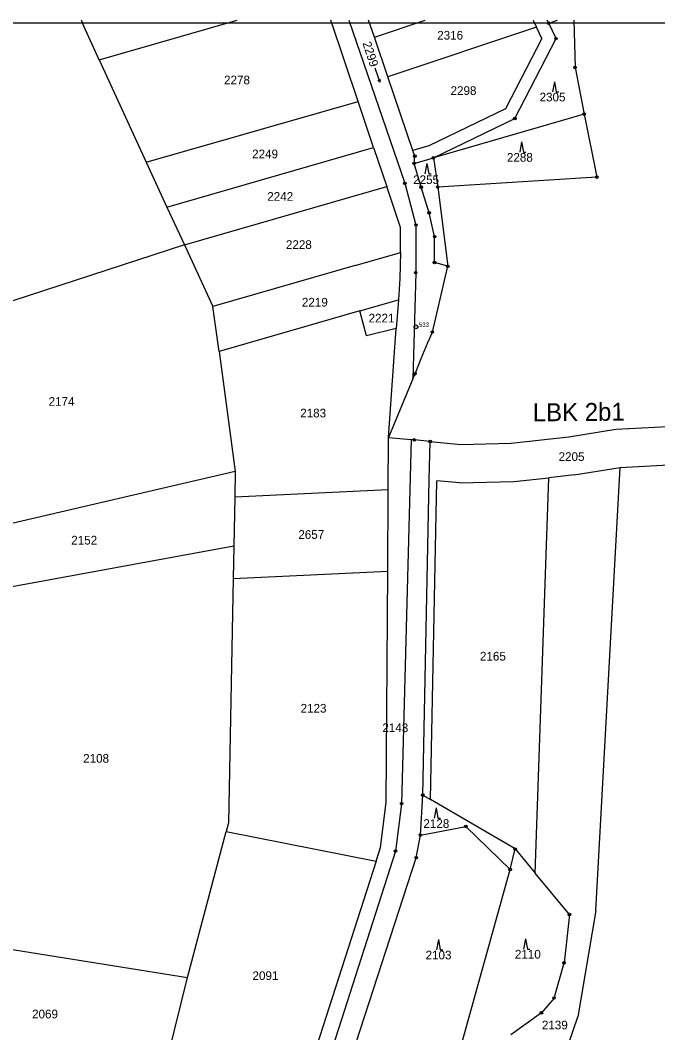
# Model space of a CAD drawing. Extents: x -566461 to -565197, y -1096302 to -1095706.
# Drawn here: x -565802.3 to -565553.3, y -1096101.6 to -1095706 of the extents above; entities that cross this region are included whole.
import ezdxf

# ---------------------------------------------------------------- set-up
doc = ezdxf.new("R2010")
doc.units = 0
for name, color, linetype in [('Vrstva 1', 7, 'Continuous'), ('Vrstva 13', 7, 'Continuous'), ('Vrstva 17', 7, 'Continuous'), ('Vrstva 18', 7, 'Continuous'), ('Vrstva 24', 7, 'Continuous'), ('Vrstva 25', 7, 'Continuous'), ('Vrstva 63', 7, 'Continuous')]:
    doc.layers.add(name, color=color, linetype=linetype)

msp = doc.modelspace()

# ---------------------------------------------------------------- linework, layer by layer
at = {"layer": 'Vrstva 1'}
for p, q in [((-565777.54, -1095708.35), (-565778.44, -1095705.99)), ((-565771.47, -1095721.51), (-565777.54, -1095708.35)), ((-565771.47, -1095721.51), (-565717.56, -1095705.99)), ((-565670.31, -1095737.74), (-565680.99, -1095705.99)), ((-565673.99, -1095705.99), (-565652.1, -1095769.69)), ((-565663.97, -1095712.64), (-565666.23, -1095705.99)), ((-565663.97, -1095712.64), (-565644.16, -1095705.99)), ((-565600.65, -1095708.75), (-565658.72, -1095728.1)), ((-565601.97, -1095705.99), (-565600.65, -1095708.75)), ((-565598.58, -1095713.08), (-565600.65, -1095708.75)), ((-565595.87, -1095707.16), (-565596.43, -1095705.99)), ((-565595.87, -1095707.16), (-565592.37, -1095705.99)), ((-565593, -1095713.17), (-565595.87, -1095707.16)), ((-565658.72, -1095728.1), (-565663.97, -1095712.64)), ((-565598.58, -1095713.08), (-565612.8, -1095740.59)), ((-565609.12, -1095744.37), (-565593, -1095713.17)), ((-565771.47, -1095721.51), (-565753.07, -1095761.44)), ((-565648.94, -1095756.88), (-565658.72, -1095728.1)), ((-565753.07, -1095761.44), (-565670.31, -1095737.74)), ((-565664.25, -1095755.72), (-565670.31, -1095737.74)), ((-565612.8, -1095740.59), (-565642.72, -1095755.05)), ((-565581.98, -1095742.65), (-565640.92, -1095759.74)), ((-565640.92, -1095759.74), (-565609.12, -1095744.37)), ((-565744.99, -1095778.97), (-565664.25, -1095755.72)), ((-565664.25, -1095755.72), (-565659.11, -1095770.99)), ((-565642.72, -1095755.05), (-565648.94, -1095756.88)), ((-565648.18, -1095759.12), (-565648.94, -1095756.88)), ((-565648.45, -1095761.92), (-565648.18, -1095759.12)), ((-565648.45, -1095761.92), (-565640.92, -1095759.74)), ((-565640.92, -1095759.74), (-565639.24, -1095771.17)), ((-565753.07, -1095761.44), (-565744.99, -1095778.97)), ((-565645.7, -1095771.21), (-565648.45, -1095761.92)), ((-565738.18, -1095793.75), (-565659.11, -1095770.99)), ((-565653.73, -1095786.97), (-565659.11, -1095770.99)), ((-565652.1, -1095769.69), (-565647.72, -1095786)), ((-565642.59, -1095781.22), (-565645.7, -1095771.21)), ((-565744.99, -1095778.97), (-565738.18, -1095793.75)), ((-565640.43, -1095790.53), (-565642.59, -1095781.22)), ((-565653.78, -1095796.72), (-565653.73, -1095786.97)), ((-565647.72, -1095786), (-565647.82, -1095804.63)), ((-565640.52, -1095800.66), (-565640.43, -1095790.53)), ((-565738.18, -1095793.75), (-565857.02, -1095832.44)), ((-565738.18, -1095793.75), (-565727.08, -1095817.82)), ((-565671.46, -1095801.81), (-565653.78, -1095796.72)), ((-565653.78, -1095796.72), (-565653.99, -1095806.9)), ((-565671.46, -1095801.81), (-565727.08, -1095817.82)), ((-565635.28, -1095802.11), (-565640.52, -1095800.66)), ((-565653.99, -1095806.9), (-565654.59, -1095815.19)), ((-565647.82, -1095804.63), (-565648.92, -1095846.12)), ((-565669.64, -1095819.55), (-565654.59, -1095815.19)), ((-565654.59, -1095815.19), (-565655.4, -1095826.46)), ((-565724.6, -1095835.47), (-565727.08, -1095817.82)), ((-565669.64, -1095819.55), (-565724.6, -1095835.47)), ((-565667.04, -1095829.24), (-565669.64, -1095819.55)), ((-565655.4, -1095826.46), (-565667.04, -1095829.24)), ((-565658.43, -1095868.97), (-565655.4, -1095826.46)), ((-565724.6, -1095835.47), (-565718.36, -1095882.24)), ((-565658.56, -1095889.49), (-565658.43, -1095868.97)), ((-565649.55, -1095869.85), (-565653.34, -1096012.12)), ((-565642.52, -1095885.6), (-565642.21, -1095870.56)), ((-565568.01, -1095880.69), (-565521.32, -1095878.21)), ((-565718.36, -1095882.24), (-565836.03, -1095909.77)), ((-565718.36, -1095882.24), (-565718.55, -1095892.34)), ((-565585.92, -1095883.62), (-565568.01, -1095880.69)), ((-565577.48, -1096053.89), (-565568.01, -1095880.69)), ((-565645.08, -1096008.78), (-565642.52, -1095885.6)), ((-565642.11, -1096010.51), (-565639.56, -1095885.89)), ((-565630.78, -1095886.75), (-565639.56, -1095885.89)), ((-565630.78, -1095886.75), (-565609.49, -1095886.27)), ((-565609.49, -1095886.27), (-565595.88, -1095884.74)), ((-565601.21, -1096039.18), (-565595.88, -1095884.74)), ((-565585.92, -1095883.62), (-565595.88, -1095884.74)), ((-565658.56, -1095889.49), (-565718.55, -1095892.34)), ((-565658.76, -1095921.2), (-565658.56, -1095889.49)), ((-565718.55, -1095892.34), (-565718.91, -1095911.52)), ((-565718.91, -1095911.52), (-565830.02, -1095931.91)), ((-565718.91, -1095911.52), (-565719.15, -1095924.11)), ((-565719.15, -1095924.11), (-565658.76, -1095921.2)), ((-565659.33, -1096011.65), (-565658.76, -1095921.2)), ((-565719.15, -1095924.11), (-565720.97, -1096019.59)), ((-565646, -1096024.36), (-565645.08, -1096008.78)), ((-565645.08, -1096008.78), (-565642.11, -1096010.51)), ((-565661.61, -1096029.27), (-565659.33, -1096011.65)), ((-565653.34, -1096012.12), (-565655.73, -1096030.58)), ((-565608.98, -1096029.79), (-565642.11, -1096010.51)), ((-565720.97, -1096019.59), (-565721.87, -1096022.99)), ((-565646, -1096024.36), (-565628.24, -1096020.97)), ((-565610.93, -1096037.81), (-565628.24, -1096020.97)), ((-565736.97, -1096079.98), (-565721.87, -1096022.99)), ((-565721.87, -1096022.99), (-565663.31, -1096034.56)), ((-565647.61, -1096033.2), (-565646, -1096024.36)), ((-565663.31, -1096034.56), (-565661.61, -1096029.27)), ((-565655.73, -1096030.58), (-565691.34, -1096141.44)), ((-565678.86, -1096129.12), (-565647.61, -1096033.2)), ((-565610.93, -1096037.81), (-565608.98, -1096029.79)), ((-565608.98, -1096029.79), (-565601.21, -1096039.18)), ((-565663.31, -1096034.56), (-565696.05, -1096136.4)), ((-565630.9, -1096109.42), (-565610.93, -1096037.81)), ((-565587.78, -1096055.41), (-565601.21, -1096039.18)), ((-565587.78, -1096055.41), (-565589.89, -1096074.25)), ((-565577.48, -1096053.89), (-565584.54, -1096095.4)), ((-565838.03, -1096063.98), (-565736.97, -1096079.98)), ((-565593.78, -1096088.03), (-565589.89, -1096074.25)), ((-565748.22, -1096125.78), (-565736.97, -1096079.98)), ((-565593.78, -1096088.03), (-565598.72, -1096093.8)), ((-565642.73, -1096265.59), (-565584.54, -1096095.4)), ((-565598.72, -1096093.8), (-565610.72, -1096102.41))]:
    msp.add_line(p, q, dxfattribs=at)
at = {"layer": 'Vrstva 13'}
for p, q in [((-565586.08, -1095705.99), (-565585.59, -1095724.47)), ((-565585.59, -1095724.47), (-565581.98, -1095742.65)), ((-565581.98, -1095742.65), (-565577.09, -1095767.26)), ((-565577.09, -1095767.26), (-565639.24, -1095771.17)), ((-565639.24, -1095771.17), (-565635.28, -1095802.11)), ((-565641.32, -1095827.8), (-565635.28, -1095802.11)), ((-565643.04, -1095831.96), (-565641.32, -1095827.8)), ((-565645.64, -1095838.21), (-565643.04, -1095831.96)), ((-565648.08, -1095844.1), (-565645.64, -1095838.21)), ((-565648.92, -1095846.12), (-565658.43, -1095868.97)), ((-565648.92, -1095846.12), (-565648.08, -1095844.1)), ((-565569.62, -1095865.76), (-565522.03, -1095863.23)), ((-565587.97, -1095868.76), (-565569.62, -1095865.76)), ((-565658.43, -1095868.97), (-565649.55, -1095869.85)), ((-565648.38, -1095869.96), (-565649.55, -1095869.85)), ((-565642.21, -1095870.56), (-565648.38, -1095869.96)), ((-565642.21, -1095870.56), (-565630.22, -1095871.73)), ((-565630.22, -1095871.73), (-565610.5, -1095871.29)), ((-565610.5, -1095871.29), (-565587.97, -1095868.76))]:
    msp.add_line(p, q, dxfattribs=at)
at = {"layer": 'Vrstva 24'}
for centre, radius in [((-565595.87, -1095707.16), 0.5), ((-565595.87, -1095707.16), 0.0327), ((-565593, -1095713.17), 0.5), ((-565593, -1095713.17), 0.0327), ((-565585.59, -1095724.47), 0.5), ((-565585.59, -1095724.47), 0.0327), ((-565609.12, -1095744.37), 0.5), ((-565609.12, -1095744.37), 0.0327), ((-565581.98, -1095742.65), 0.5), ((-565581.98, -1095742.65), 0.0327), ((-565648.18, -1095759.12), 0.5), ((-565648.18, -1095759.12), 0.0327), ((-565640.92, -1095759.74), 0.5), ((-565640.92, -1095759.74), 0.0327), ((-565648.45, -1095761.92), 0.5), ((-565648.45, -1095761.92), 0.0327), ((-565577.09, -1095767.26), 0.5), ((-565577.09, -1095767.26), 0.0327), ((-565652.1, -1095769.69), 0.5), ((-565652.1, -1095769.69), 0.0327), ((-565645.7, -1095771.21), 0.5), ((-565645.7, -1095771.21), 0.0327), ((-565639.24, -1095771.17), 0.5), ((-565639.24, -1095771.17), 0.0327), ((-565642.59, -1095781.22), 0.5), ((-565642.59, -1095781.22), 0.0327), ((-565647.72, -1095786), 0.5), ((-565647.72, -1095786), 0.0327), ((-565640.43, -1095790.53), 0.5), ((-565640.43, -1095790.53), 0.0327), ((-565640.52, -1095800.66), 0.5), ((-565640.52, -1095800.66), 0.0327), ((-565635.28, -1095802.11), 0.5), ((-565635.28, -1095802.11), 0.0327), ((-565647.82, -1095804.63), 0.5), ((-565647.82, -1095804.63), 0.0327), ((-565647.73, -1095825.8), 0.75), ((-565647.73, -1095825.8), 0.0327), ((-565641.32, -1095827.8), 0.5), ((-565641.32, -1095827.8), 0.0327), ((-565648.08, -1095844.1), 0.5), ((-565648.08, -1095844.1), 0.0327), ((-565648.38, -1095869.96), 0.5), ((-565648.38, -1095869.96), 0.0327), ((-565642.21, -1095870.56), 0.5), ((-565642.21, -1095870.56), 0.0327), ((-565645.08, -1096008.78), 0.5), ((-565645.08, -1096008.78), 0.0327), ((-565653.34, -1096012.12), 0.5), ((-565653.34, -1096012.12), 0.0327), ((-565628.24, -1096020.97), 0.5), ((-565628.24, -1096020.97), 0.0327), ((-565646, -1096024.36), 0.5), ((-565646, -1096024.36), 0.0327), ((-565608.98, -1096029.79), 0.5), ((-565655.73, -1096030.58), 0.5), ((-565655.73, -1096030.58), 0.0327), ((-565647.61, -1096033.2), 0.5), ((-565647.61, -1096033.2), 0.0327), ((-565608.98, -1096029.79), 0.0327), ((-565610.93, -1096037.81), 0.5), ((-565610.93, -1096037.81), 0.0327), ((-565587.78, -1096055.41), 0.5), ((-565587.78, -1096055.41), 0.0327), ((-565589.89, -1096074.25), 0.5), ((-565589.89, -1096074.25), 0.0327), ((-565593.78, -1096088.03), 0.5), ((-565593.78, -1096088.03), 0.0327), ((-565598.72, -1096093.8), 0.5), ((-565598.72, -1096093.8), 0.0327)]:
    msp.add_circle(centre, radius, dxfattribs=at)
at = {"layer": 'Vrstva 25'}
for p, q in [((-565663.8, -1095724.53), (-565661.84, -1095730.21)), ((-565593.63, -1095729.99), (-565594.36, -1095733.99)), ((-565593.63, -1095729.99), (-565592.9, -1095733.99)), ((-565592.9, -1095733.99), (-565591.9, -1095733.99)), ((-565606.47, -1095753.55), (-565607.2, -1095757.55)), ((-565606.47, -1095753.55), (-565605.74, -1095757.55)), ((-565605.74, -1095757.55), (-565604.74, -1095757.55)), ((-565643.49, -1095761.94), (-565644.22, -1095765.94)), ((-565643.49, -1095761.94), (-565642.76, -1095765.94)), ((-565642.76, -1095765.94), (-565641.76, -1095765.94)), ((-565639.85, -1096013.73), (-565640.58, -1096017.73)), ((-565639.85, -1096013.73), (-565639.12, -1096017.73)), ((-565639.12, -1096017.73), (-565638.12, -1096017.73)), ((-565604.93, -1096064.9), (-565605.67, -1096068.9)), ((-565604.93, -1096064.9), (-565604.2, -1096068.9)), ((-565638.96, -1096065.22), (-565639.7, -1096069.22)), ((-565638.96, -1096065.22), (-565638.23, -1096069.22)), ((-565604.2, -1096068.9), (-565603.2, -1096068.9)), ((-565638.23, -1096069.22), (-565637.23, -1096069.22))]:
    msp.add_line(p, q, dxfattribs=at)
msp.add_lwpolyline([(-565661.7, -1095729.1), (-565661.84, -1095730.21), (-565662.64, -1095729.42)], dxfattribs=at)
at = {"layer": 'Vrstva 63'}
msp.add_line((-566458.38, -1095707.03), (-565198.38, -1095707.03), dxfattribs=at)

# ---------------------------------------------------------------- texts
at = {"layer": 'Vrstva 1'}
msp.add_text('LBK 2b1', height=7, rotation=0.4339, dxfattribs=at).set_placement((-565602.06, -1095862.71))
at = {"layer": 'Vrstva 17'}
msp.add_text('533', height=1.7, dxfattribs=at).set_placement((-565646.54, -1095825.79))
at = {"layer": 'Vrstva 18'}
for s, p in [('2316', (-565639.42, -1095713.56)), ('2278', (-565722.7, -1095731.03)), ('2298', (-565634.21, -1095735.18)), ('2305', (-565599.43, -1095737.7)), ('2249', (-565711.73, -1095759.93)), ('2288', (-565612.19, -1095761.26)), ('2255', (-565648.82, -1095769.99)), ('2242', (-565705.81, -1095776.53)), ('2228', (-565698.53, -1095795.35)), ('2219', (-565692.29, -1095817.87)), ('2221', (-565666.23, -1095824.07)), ('2174', (-565791.23, -1095856.64)), ('2183', (-565692.95, -1095861.17)), ('2205', (-565592, -1095878.18)), ('2657', (-565693.67, -1095908.62)), ('2152', (-565782.4, -1095910.84)), ('2165', (-565622.73, -1095956.18)), ('2123', (-565692.8, -1095976.52)), ('2143', (-565660.85, -1095984.11)), ('2108', (-565777.74, -1095996.09)), ('2128', (-565644.82, -1096021.56)), ('2103', (-565643.97, -1096072.93)), ('2110', (-565609.07, -1096072.61)), ('2091', (-565711.58, -1096080.99)), ('2069', (-565797.69, -1096095.98)), ('2139', (-565598.53, -1096100.27))]:
    msp.add_text(s, height=3.4, dxfattribs=at).set_placement(p)
msp.add_text('2299', height=3.4, rotation=288, dxfattribs=at).set_placement((-565668.66, -1095714.9))

doc.saveas('drawing.dxf')
